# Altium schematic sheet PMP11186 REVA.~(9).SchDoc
size 431 x 279 mm; Date: Not shown in title block; ApprovedBy: Not shown in title block; CheckedBy: Not shown in title block; Author: Not shown in title block; CompanyName: Not shown in title block; Engineer: Not shown in title block; Organization: Not shown in title block; Address1: Not shown in title block; Address2: Not shown in title block; Address3: Not shown in title block; Address4: Not shown in title block; DocumentNumber: 1; Revision: Use project parameter SCH_Rev; SheetNumber: 1; SheetTotal: 1; PageSetup: Record=PageOptions¦CenterHorizontal=True¦CenterVertical=True¦PrintScale=1.00¦XCorrection=1.00¦YCorrection=1.00¦PrintKind=0¦BorderSize=5000000¦LeftOffset=0¦BottomOffset=0¦Orientation=2¦PaperLength=1000¦PaperWidth=1000¦Scale=100¦PaperSource=15¦PrintQuality=600¦MediaType=1¦DitherType=10¦PaperKind=Letter¦PrintScaleMode=1
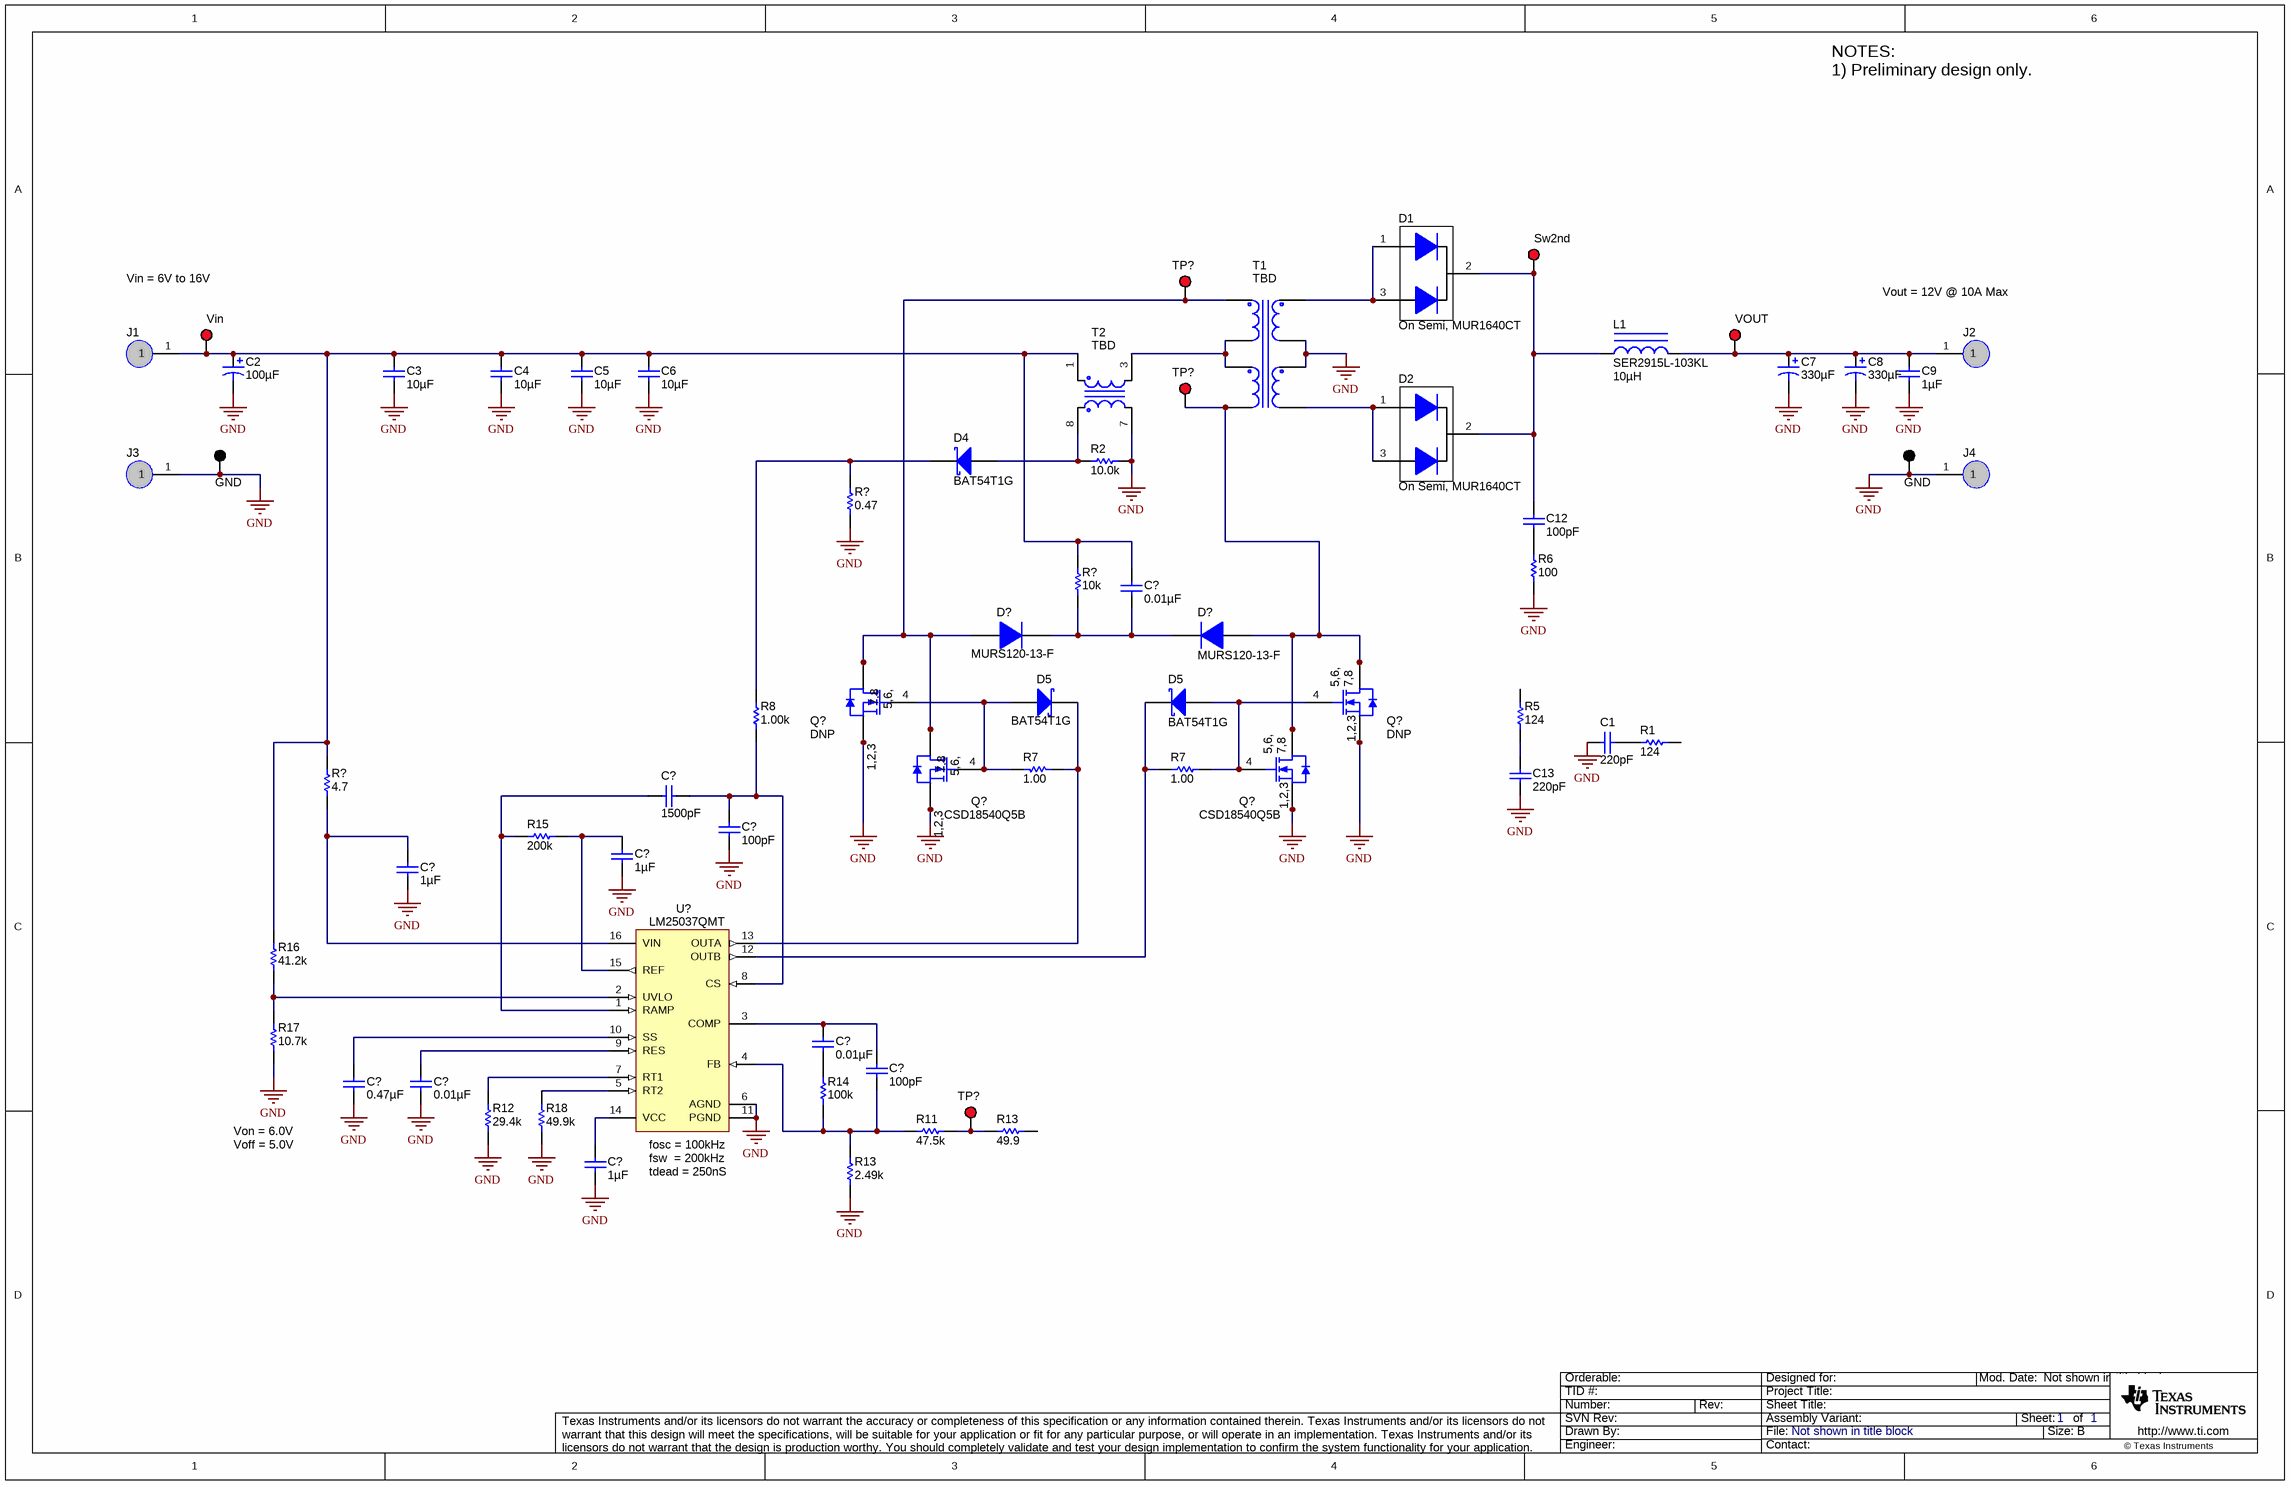
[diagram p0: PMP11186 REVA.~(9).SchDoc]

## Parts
(Parts that share a designator on the sheet are numbered #1, #2 ... from top to bottom, then left to right.)
C1  ValueDisplayed: 220pF  [0805_HV]  (hidden comment: GRM2165C2A221JA01D)
C2  ValueDisplayed: 100µF  [CAPSMT_62_KE0]  (hidden comment: EMVA101ATR101MKE0S)
C3  ValueDisplayed: 10µF  [2220]  (hidden comment: C5750X7R1H106M)
C4  ValueDisplayed: 10µF  [2220]  (hidden comment: C5750X7R1H106M)
C5  ValueDisplayed: 10µF  [2220]  (hidden comment: C5750X7R1H106M)
C6  ValueDisplayed: 10µF  [2220]  (hidden comment: C5750X7R1H106M)
C7  ValueDisplayed: 330µF  [SM_RADIAL_H13]  (hidden comment: EEV-FK1H331Q)
C8  ValueDisplayed: 330µF  [SM_RADIAL_H13]  (hidden comment: EEV-FK1H331Q)
C9  ValueDisplayed: 1µF  [0805_HV]  (hidden comment: GRM21BR71H105KA12L)
C12  ValueDisplayed: 100pF  [0805_HV]  (hidden comment: 08051A101FAT2A)
C13  ValueDisplayed: 220pF  [0805_HV]  (hidden comment: GRM2165C2A221JA01D)
C?#1  ValueDisplayed: 0.01µF  [0805_HV]  (hidden comment: C2012X7R2A103M)
C?#2  ValueDisplayed: 1500pF  [0603]  (hidden comment: C1608C0G1H152J)
C?#3  ValueDisplayed: 100pF  [0603]  (hidden comment: C1608C0G1H101J)
C?#4  ValueDisplayed: 1µF  [0805_HV]  (hidden comment: C2012X7R1E105K)
C?#5  ValueDisplayed: 1µF  [0805_HV]  (hidden comment: C2012X7R1E105K)
C?#6  ValueDisplayed: 0.01µF  [0603]  (hidden comment: C1608X7R1H103K)
C?#7  ValueDisplayed: 100pF  [0603]  (hidden comment: C1608C0G1H101J)
C?#8  ValueDisplayed: 0.47µF  [0603]  (hidden comment: C1608X5R1A474K)
C?#9  ValueDisplayed: 0.01µF  [0603]  (hidden comment: C1608X7R1H103K)
C?#10  ValueDisplayed: 1µF  [0805_HV]  (hidden comment: C2012X7R1E105K)
D1  On Semi, MUR1640CT  [TO-220AB]
D2  On Semi, MUR1640CT  [TO-220AB]
D4  BAT54T1G  [SOD-123]
D5#1  BAT54T1G  [SOD-123]
D5#2  BAT54T1G  [SOD-123]
D?#1  MURS120-13-F  [SMB]
D?#2  MURS120-13-F  [SMB]
GND#1  5001  [Keystone5001]  (value not drawn)
GND#2  5001  [Keystone5001]  (value not drawn)
J1  Vin = 6V to 16V  [3144-2-00-21-00-00-08-0]
J2  Vout = 12V @ 10A Max  [3144-2-00-21-00-00-08-0]
J3  3144-2-00-21-00-00-08-0  [3144-2-00-21-00-00-08-0]  (value not drawn)
J4  3144-2-00-21-00-00-08-0  [3144-2-00-21-00-00-08-0]  (value not drawn)
L1  SER2915L-103KL  ValueDisplayed: 10µH  [SER2915]
Q?#1  DNP  [TRANS_NexFET_Q5B]
Q?#2  DNP  [TRANS_NexFET_Q5B]
Q?#3  CSD18540Q5B  [TRANS_NexFET_Q5B]
Q?#4  CSD18540Q5B  [TRANS_NexFET_Q5B]
R1  value 124  [2512M]  (hidden comment: ERJ-1TNF1240U)
R2  value 10.0k  [0603]  (hidden comment: CRCW060310K0FKEA)
R5  value 124  [2512M]  (hidden comment: ERJ-1TNF1240U)
R6  value 100  [1206]  (hidden comment: CRCW1206100RFKEA)
R7#1  value 1.00  [0603]  (hidden comment: CRCW06031R00FKEA)
R7#2  value 1.00  [0603]  (hidden comment: CRCW06031R00FKEA)
R8  value 1.00k  [0603]  (hidden comment: CRCW06031K00FKEA)
R11  ValueDisplayed: 47.5k  [0603]  (hidden comment: CRCW060347K5FKEA)
R12  ValueDisplayed: 29.4k  [0603]  (hidden comment: CRCW060329K4FKEA)
R13#1  ValueDisplayed: 49.9  [0603]  (hidden comment: CRCW060349R9FKEA)
R13#2  value 2.49k  [0603]  (hidden comment: CRCW06032K49FKEA)
R14  value 100k  [0603]  (hidden comment: CRCW0603100KFKEA)
R15  ValueDisplayed: 200k  [0603]  (hidden comment: CRCW0603200KFKEA)
R16  ValueDisplayed: 41.2k  [0603]  (hidden comment: CRCW060341K2FKEA)
R17  ValueDisplayed: 10.7k  [0603]  (hidden comment: CRCW060310K7FKEA)
R18  ValueDisplayed: 49.9k  [0603]  (hidden comment: CRCW060349K9FKEA)
R?#1  ValueDisplayed: 0.47  [1206]  (hidden comment: ERJ-8RQFR47V)
R?#2  ValueDisplayed: 10k  [2512]  (hidden comment: CRCW251210K0JNEG)
R?#3  ValueDisplayed: 4.7  [0805_HV]  (hidden comment: ERJ-6GEYJ4R7V)
Sw2nd  5000  [Keystone5000]  (value not drawn)
T1  PartNumber: TBD  (hidden comment: Pulse, PA0901)
T2  PartNumber: TBD  [P82xx]  (hidden comment: Pulse, PB0026NL)
TP?#1  5000  [Keystone5000]  (value not drawn)
TP?#2  5000  [Keystone5000]  (value not drawn)
TP?#3  5000  [Keystone5000]  (value not drawn)
U?  LM25037QMT  [MTC16_N]
Vin  5000  [Keystone5000]  (value not drawn)
VOUT  5000  [Keystone5000]  (value not drawn)

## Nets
GND: C1.1 C2.2(-) C3.2 C4.2 C5.2 C6.2 C7.2(-) C8.2(-) C9.2 C13.2 C?#3.2 C?#4.2 C?#5.2 C?#8.2 C?#9.2 C?#10.2 GND#1.1 GND#2.1 J3.1 J4.1 Q?#1.1(S) Q?#1.2(S) Q?#1.3(S) Q?#2.1(S) Q?#2.2(S) Q?#2.3(S) Q?#3.1(S) Q?#3.2(S) Q?#3.3(S) Q?#4.1(S) Q?#4.2(S) Q?#4.3(S) R2.2 R6.1 R12.1 R13#2.1 R17.1 R18.1 R?#1.1 T1.6 T1.7 T2.7 U?.6(AGND) U?.11(PGND)
NetC1_2: C1.2 R1.2
NetC2_1: C2.1(+) C3.1 C4.1 C5.1 C6.1 C?#1.1 J1.1 R16.2 R?#2.2 R?#3.2 T2.1 Vin.1
NetC7_1: C7.1(+) C8.1(+) C9.1 J2.1 L1.2 VOUT.1
NetC12_1: C12.1 D1.2(K) D2.2(K) L1.1 Sw2nd.1
NetC12_2: C12.2 R6.2
NetC13_1: C13.1 R5.1
NetC?#1_2: C?#1.2 D?#1.1(K) D?#2.1(K) R?#2.1
NetC?#2_1: C?#2.1 R15.1 U?.1(RAMP)
NetC?#2_2: C?#2.2 C?#3.1 R8.1 U?.8(CS)
NetC?#4_1: C?#4.1 R15.2 U?.15(REF)
NetC?#5_1: C?#5.1 R?#3.1 U?.16(VIN)
NetC?#6_1: C?#6.1 C?#7.1 U?.3(COMP)
NetC?#6_2: C?#6.2 R14.2
NetC?#7_2: C?#7.2 R11.1 R13#2.2 R14.1 U?.4(FB)
NetC?#8_1: C?#8.1 U?.10(SS)
NetC?#9_1: C?#9.1 U?.9(RES)
NetC?#10_1: C?#10.1 U?.14(VCC)
NetD1_1: D1.1(A) D1.3(A) T1.5
NetD2_1: D2.1(A) D2.3(A) T1.8
NetD4_1: D4.1(K) R8.2 R?#1.2
NetD4_2: D4.2(A) R2.1 T2.8
NetD5#1_1: D5#1.1(K) R7#1.1 U?.13(OUTA)
NetD5#1_2: D5#1.2(A) Q?#1.4(G) Q?#3.4(G) R7#1.2
NetD5#2_1: D5#2.1(K) R7#2.1 U?.12(OUTB)
NetD5#2_2: D5#2.2(A) Q?#2.4(G) Q?#4.4(G) R7#2.2
NetD?#1_2: D?#1.2(A) Q?#1.5(D) Q?#1.6(D) Q?#1.7(D) Q?#1.8(D) Q?#3.5(D) Q?#3.6(D) Q?#3.7(D) Q?#3.8(D) T1.1 TP?#1.1
NetD?#2_2: D?#2.2(A) Q?#2.5(D) Q?#2.6(D) Q?#2.7(D) Q?#2.8(D) Q?#4.5(D) Q?#4.6(D) Q?#4.7(D) Q?#4.8(D) T1.4 TP?#2.1
NetR11_2: R11.2 R13#1.2 TP?#3.1
NetR12_2: R12.2 U?.7(RT1)
NetR16_1: R16.1 R17.2 U?.2(UVLO)
NetR18_2: R18.2 U?.5(RT2)
NetT1_2: T1.2 T1.3 T2.3

Not connected (* = marked no-connect by the designer): R1 1; R5 2; R13#1 1

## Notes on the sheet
- NOTES:
  1) Preliminary design only.
- Von = 6.0V
- Voff = 5.0V
- fsw  = 200kHz
- tdead = 250nS
- (near U?) fosc = 100kHz

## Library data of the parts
C1 C13 = GRM2165C2A221JA01D: CAP, CERM, 220pF, 100V, +/-5%, C0G/NP0, 0805; Manufacturer: MuRata; Polarized: N; CompType: Capacitor; U/M: EA; Cap_F: 0.00000000022; Tolerance_%: 5; VDC_V: 100; TaMin_C: -55; TaMax_C: 125; Cap_Case: 0805
C2 = EMVA101ATR101MKE0S: CAP, AL, 100uF, 100V, +/-20%, SMD; Manufacturer: Nippon Chemi-Con; Polarized: Y; CompType: Capacitor; U/M: EA; Cap_F: 0.0001; Tolerance_%: 20; VDC_V: 100; IRMS_A: 0.44; TaMin_C: -40; TaMax_C: 85; Cap_Case: KE0
C3-C6 = C5750X7R1H106M: CAP, CERM, 10uF, 50V, +/-20%, X7R, 2220; Manufacturer: TDK; Polarized: N; CompType: Capacitor; U/M: EA; Cap_F: 0.00001; Tolerance_%: 20; ESR_Ohm: 0.003; Value1: 0.003 ohm; VDC_V: 50; IRMS_A: 5.5; TaMin_C: -55; TaMax_C: 125
C7 C8 = EEV-FK1H331Q: CAP, AL, 330uF, 50V, +/-20%, 0.12 ohm, SMD; Manufacturer: Panasonic; Polarized: Y; CompType: Capacitor; U/M: EA; Cap_F: 0.00033; Tolerance_%: 20; VDC_V: 50; ESR_Ohm: 0.12; IRMS_A: 0.9; TaMin_C: -55; TaMax_C: 105; Cap_Case: H13
C9 = GRM21BR71H105KA12L: CAP, CERM, 1uF, 50V, +/-10%, X7R, 0805; Manufacturer: MuRata; Polarized: N; CompType: Capacitor; U/M: EA; Cap_F: 0.000001; Tolerance_%: 10; VDC_V: 50; TaMin_C: -55; TaMax_C: 125; Cap_Case: 0805
C12 = 08051A101FAT2A: CAP, CERM, 100pF, 100V, +/-1%, C0G/NP0, 0805; Manufacturer: AVX; Polarized: N; CompType: Capacitor; U/M: EA; Cap_F: 0.0000000001; Tolerance_%: 1; ESR_Ohm: 0.356; Value1: 0.356 ohm; VDC_V: 100; TaMin_C: -55; TaMax_C: 125; Cap_Case: 0805
C?#1 = C2012X7R2A103M: CAP, CERM, 0.01 µF, 100 V, +/- 20%, X7R, 0805; Manufacturer: TDK; Polarized: N; CompType: Capacitor; Value: 0.01uF; U/M: EA; Cap_F: 0.00000001; Tolerance_%: 20; ESR_ohm: 0.0571; Value1: 0.0571 ohm; VDC_V: 100; Value2: 100V; TaMin_C: -55; TaMax_C: 125; Cap_Case: 0805
C?#2 = C1608C0G1H152J: CAP, CERM, 1500 pF, 50 V, +/- 5%, C0G/NP0, 0603; Manufacturer: TDK; Polarized: N; CompType: Capacitor; Value: 1500pF; U/M: EA; Cap_F: 0.0000000015; Tolerance_%: 5; ESR_ohm: 0.039; Value1: 0.039 ohm; VDC_V: 50; Value2: 50V; TaMin_C: -55; TaMax_C: 125
C?#3 C?#7 = C1608C0G1H101J: CAP, CERM, 100 pF, 50 V, +/- 5%, C0G/NP0, 0603; Manufacturer: TDK; Polarized: N; CompType: Capacitor; Value: 100pF; U/M: EA; Cap_F: 0.0000000001; Tolerance_%: 5; ESR_ohm: 0.1679; Value1: 0.1679 ohm; VDC_V: 50; Value2: 50V; TaMin_C: -55; TaMax_C: 125
C?#4 C?#5 C?#10 = C2012X7R1E105K: CAP, CERM, 1 µF, 25 V, +/- 10%, X7R, 0805; Manufacturer: TDK; Polarized: N; CompType: Capacitor; Value: 1uF; U/M: EA; Cap_F: 0.000001; Tolerance_%: 10; ESR_ohm: 0.0075; Value1: 0.0075 ohm; VDC_V: 25; Value2: 25V; TaMin_C: -55; TaMax_C: 125; Cap_Case: 0805
C?#6 C?#9 = C1608X7R1H103K: CAP, CERM, 0.01 µF, 50 V, +/- 10%, X7R, 0603; Manufacturer: TDK; Polarized: N; CompType: Capacitor; Value: 0.01uF; U/M: EA; Cap_F: 0.00000001; Tolerance_%: 10; ESR_ohm: 0.0539; Value1: 0.0539 ohm; VDC_V: 50; Value2: 50V; TaMin_C: -55; TaMax_C: 125
C?#8 = C1608X5R1A474K: CAP, CERM, 0.47 µF, 10 V, +/- 10%, X5R, 0603; Manufacturer: TDK; Polarized: N; CompType: Capacitor; Value: 0.47uF; U/M: EA; Cap_F: 0.00000047; Tolerance_%: 10; ESR_ohm: 0.0101; Value1: 0.0101 ohm; Value2: 10V; TaMin_C: -55; TaMax_C: 85
D1 D2 = MURH860CTG: Diode, Ultrafast, 600V, 4A, TH; Manufacturer: ON Semiconductor; RJC_CperW: 3; Vf_V: 2.8; Io_A: 4; Vr_V: 600; TJMax_C: 175; U/M: EA
D4 = BAT54T1G: Diode, Schottky, 30V, 0.2A, SOD-123; Manufacturer: ON Semiconductor; Value: 0.8V; U/M: EA; Vf_V: 0.8; Io_A: 0.2; Vr_V: 30; TJmax_C: 125; RJC_CperW: 174
D5#1 D5#2 = BAT54T1G: Diode, Schottky, 30V, 0.2A, SOD-123; Manufacturer: ON Semi; Value: 0.8V; U/M: EA; Vf_V: 0.8; Io_A: 0.2; Vr_V: 30; TJmax_C: 125; RJC_CperW: 174
D?#1 D?#2 = MURS120-13-F: Diode, Superfast Rectifier, 200 V, 1 A, SMB; Manufacturer: Diodes Inc.; U/M: EA; Vf_V: 0.875; Value: 200V; Value1: 1A; Value2: 0.875V; Io_A: 1; Vr_V: 200; TJmax_C: 175
GND#1 GND#2 = 5001: Test Point, TH, Miniature, Black; Manufacturer: Keystone; CompType: Test Point Loop; U/M: EA
J1-J4 = 3144-2-00-21-00-00-08-0: CIRCUIT PIN PRNTD .188" .084"; Manufacturer: Mill -Max; SymbolVersion: 2011 - 12 - 16; SymbolCreator: cdnlsc; U/M: EA
L1 = SER2915L-103KL: Inductor, Shielded E Core, Ferrite, 10uH, 13A, 0.0015 ohm, SMD; Manufacturer: Coilcraft; Ind_H: 10.0E-6; Imax_A: 13; Irms: 30A @ 40C rise; Isat: 13A @ 10% inductance drop; DCR_ohm: 0.0015; U/M: EA
Q?#1 Q?#2 = CSD18540Q5B: MOSFET, DNP, SON 5x6mm; Manufacturer: Texas Instruments; Alternate Manufacturer: None; U/M: EA; ChType: N; Value: 60V; IdsMax_A: 28
Q?#3 Q?#4 = CSD18540Q5B: MOSFET, N-CH, 60 V, 28 A, SON 5x6mm; Manufacturer: Texas Instruments; Alternate Manufacturer: None; U/M: EA; ChType: N; Value: 60V; VdsMax_V: 60; Value1: 0.0033 ohm; Rdson45_ohm: 0.0033; Value2: 41 nC; QgTyp_nC: 41; Vgs_V: 20; IdsMax_A: 28
R1 R5 = ERJ-1TNF1240U: RES, 124 ohm, 1%, 1W, 2512; Manufacturer: Panasonic; CompType: Resistor; Value_Code: 124R; Tolerance_%: 1; VDC_V: 200; TempCo: 100 ppm/C; EIA_Code: E96; U/M: EA
R2 = CRCW060310K0FKEA: RES, 10.0k ohm, 1%, 0.1W, 0603; Manufacturer: Vishay-Dale; CompType: Resistor; Res_ohm: 10000; Value_Code: 10k0; Tolerance_%: 1; Power_W: 0.1; VDC_V: 75; TempCo: 100 ppm/C; EIA_Code: E96; U/M: EA
R6 = CRCW1206100RFKEA: RES, 100 ohm, 1%, 0.25W, 1206; Manufacturer: Vishay-Dale; CompType: Resistor; Value_Code: 100R; Tolerance_%: 1; Power_W: 0.25; VDC_V: 200; TempCo: 100 ppm/C; EIA_Code: E96; U/M: EA
R7#1 R7#2 = CRCW06031R00FKEA: RES, 1.00 ohm, 1%, 0.1W, 0603; Manufacturer: Vishay-Dale; CompType: Resistor; Res_ohm: 1; Value_Code: 1R00; Power_W: 0.1; VDC_V: 75; TempCo: 100 ppm/C; EIA_Code: E96; U/M: EA
R8 = CRCW06031K00FKEA: RES, 1.00k ohm, 1%, 0.1W, 0603; Manufacturer: Vishay-Dale; CompType: Resistor; Res_ohm: 1000; Value_Code: 1k00; Tolerance_%: 1; Power_W: 0.1; VDC_V: 75; TempCo: 100 ppm/C; EIA_Code: E96; U/M: EA
R11 = CRCW060347K5FKEA: RES, 47.5 k, 1%, 0.1 W, 0603; Manufacturer: Vishay-Dale; CompType: Resistor; Value: 47.5k; Res_ohm: 47500; Value_Code: 47k5; Tolerance_%: 1; Power_W: 0.1; Value2: 0.1W; VDC_V: 75; TempCo: 100 ppm/C; EIA_Code: E96; U/M: EA
R12 = CRCW060329K4FKEA: RES, 29.4 k, 1%, 0.1 W, 0603; Manufacturer: Vishay-Dale; CompType: Resistor; Value: 29.4k; Res_ohm: 29400; Value_Code: 29k4; Tolerance_%: 1; Power_W: 0.1; Value2: 0.1W; VDC_V: 75; TempCo: 100 ppm/C; EIA_Code: E96; U/M: EA
R13#1 = CRCW060349R9FKEA: RES, 49.9, 1%, 0.1 W, 0603; Manufacturer: Vishay-Dale; CompType: Resistor; Value: 49.9; Value_Code: 49R9; Tolerance_%: 1; Power_W: 0.1; Value2: 0.1W; VDC_V: 75; TempCo: 100 ppm/C; EIA_Code: E96; U/M: EA
R13#2 = CRCW06032K49FKEA: RES, 2.49k ohm, 1%, 0.1W, 0603; Manufacturer: Vishay-Dale; CompType: Resistor; Res_ohm: 2490; Value_Code: 2k49; Tolerance_%: 1; Power_W: 0.1; VDC_V: 75; TempCo: 100 ppm/C; EIA_Code: E96; U/M: EA
R14 = CRCW0603100KFKEA: RES, 100k ohm, 1%, 0.1W, 0603; Manufacturer: Vishay-Dale; CompType: Resistor; Res_ohm: 100000; Tolerance_%: 1; Power_W: 0.1; VDC_V: 75; TempCo: 100 ppm/C; EIA_Code: E96; U/M: EA
R15 = CRCW0603200KFKEA: RES, 200 k, 1%, 0.1 W, 0603; Manufacturer: Vishay-Dale; CompType: Resistor; Value: 200k; Res_ohm: 200000; Tolerance_%: 1; Power_W: 0.1; Value2: 0.1W; VDC_V: 75; TempCo: 100 ppm/C; EIA_Code: E96; U/M: EA
R16 = CRCW060341K2FKEA: RES, 41.2 k, 1%, 0.1 W, 0603; Manufacturer: Vishay-Dale; CompType: Resistor; Value: 41.2k; Res_ohm: 41200; Value_Code: 41k2; Tolerance_%: 1; Power_W: 0.1; Value2: 0.1W; VDC_V: 75; TempCo: 100 ppm/C; EIA_Code: E96; U/M: EA
R17 = CRCW060310K7FKEA: RES, 10.7 k, 1%, 0.1 W, 0603; Manufacturer: Vishay-Dale; CompType: Resistor; Value: 10.7k; Res_ohm: 10700; Value_Code: 10k7; Tolerance_%: 1; Power_W: 0.1; Value2: 0.1W; VDC_V: 75; TempCo: 100 ppm/C; EIA_Code: E96; U/M: EA
R18 = CRCW060349K9FKEA: RES, 49.9 k, 1%, 0.1 W, 0603; Manufacturer: Vishay-Dale; CompType: Resistor; Value: 49.9k; Res_ohm: 49900; Value_Code: 49k9; Tolerance_%: 1; Power_W: 0.1; Value2: 0.1W; VDC_V: 75; TempCo: 100 ppm/C; EIA_Code: E96; U/M: EA
R?#1 = ERJ-8RQFR47V: RES, 0.47, 1%, 0.25 W, 1206; Manufacturer: Panasonic; CompType: Resistor; Value: 0.47; Value_Code: R470; Tolerance_%: 1; Power_W: 0.25; Value2: 0.25W; TempCo: 250 ppm/C; EIA_Code: E96; U/M: EA
R?#2 = CRCW251210K0JNEG: RES, 10 k, 5%, 1 W, 2512; Manufacturer: Vishay-Dale; CompType: Resistor; Value: 10k; Res_ohm: 10000; Value_Code: 10k0; Tolerance_%: 5; Power_W: 1; Value2: 1W; VDC_V: 500; TempCo: 200 ppm/C; EIA_Code: E24; U/M: EA
R?#3 = ERJ-6GEYJ4R7V: RES, 4.7, 5%, 0.125 W, 0805; Manufacturer: Panasonic; CompType: Resistor; Value: 4.7; Value_Code: 4R70; Tolerance_%: 5; Power_W: 0.125; Value2: 0.125W; VDC_V: 150; TempCo: 600 ppm/C; EIA_Code: E24; U/M: EA
Sw2nd TP?#1-TP?#3 Vin VOUT = 5000: Test Point, TH, Miniature, Red; Manufacturer: Keystone; CompType: Test Point Loop; U/M: EA
T1 = XFMR_2_2: 2 Input 2 Output XFMR; Manufacturer: Used in BOM report; CompType: Transformer; U/M: EA
T2 = P8209NL: SMT Current Sense Tranformer; Manufacturer: Pulse Engineering; CompType: Transformer; Ns1toNp: 1:125; Rp: 6 mOhm; Rs1: 6.5 Ohm; SymbolCreator: codlsc; U/M: EA
U? = LM25037QMT: Dual-Mode PWM Controller With Alternating Outputs, Automotive Grade, 16-pin TSSOP; Manufacturer: Texas Instruments; PackageTopMarking: NSUZXYTT*M25037*MT; PowerWise: Y; CompType: Switcher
